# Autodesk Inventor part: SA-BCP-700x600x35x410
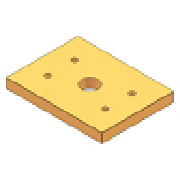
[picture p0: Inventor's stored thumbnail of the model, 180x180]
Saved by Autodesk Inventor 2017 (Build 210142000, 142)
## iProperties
Created: 2016-02
Part Number: SA-BCP-700x600x35x410
Material: S 55 C
Description: Bottom Clamping Plate
Document SubType Name: Modeling
Designer: Sandeep
Standard Revision: 1
Manufacturer: FUTABA
Language: en-US
Size Designation: 700x600x35x410
Categories: <MemberInstance><Categories><Category DisplayName="Mold" InternalName="349578f2-f4d4-4954-8c09-8e99297a61c0" Mnemonic="MOLD"><Category DisplayName="Mold Plates"
Density: 7.85 g/cm^3
Appearance: Orange (Pale)
IsCustomPart: 1
Author: Sandeep
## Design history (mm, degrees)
sketch "Sketch1"
  geometry: L1 (-300, 350)-(300, 350); L2 (300, 350)-(300, -350); L3 (300, -350)-(-300, -350); L4 (-300, -350)-(-300, 350); C1 r 17.5 at (0, 0); 4 further points
  constraints: 8 end point, 2 midpoint, 2 parallel, 1 centre point, 1 coincident, 1 horizontal, 1 horizontal alignment, 1 perpendicular, 1 vertical alignment
  dimensions: "d72" = 600 distance between parallel lines of L2 L4 (= W_); "d73" = 700 distance between parallel lines of L3 L1 (= L); "d74" = 35 diameter of C1 (= dB); "d75" = 205 horizontal distance of point (0, 0) point (-205, 243) (= 0.5 x S1_W); "d76" = 243 vertical distance of point (0, 0) point (-205, 243) (= 0.5 x S1_L)
body "Solid1"
extrude "Extrusion1" new body sketch "Sketch1" distance "d77" = 35 (= H_); taper "d78" = 0 deg
hole "Hole1" sketch "Sketch1" diameter "d79" = 18 (= S1_d1); stored, may be unused: countersink angle "d83" = 90 deg, drill point angle "d85" = 0 deg; dims "d80" = 6, "d81" = 26 (= S1_d2), "d82" = 17.5 (= S1_k), "d84" = 35 (= H_)
pattern_linear "Rectangular Pattern1" dims "d88" = 243 (computed from S1_L, Ns), "d91" = 410 (computed from S1_W, Nw)
extrude "Extrusion2" cut sketch "Sketch1" distance "d92" = 35 (= H_); taper "d93" = 0 deg
chamfer "Chamfer1" distance "d94" = 0.5; stored, may be unused: second distance "d95" = 2, angle "d96" = 45 deg
other parameters: "L" = 700 [user parameter; used in 1 equation term], "W_" = 600 [user parameter; used in 1 equation term], "H_" = 35 [user parameter; used in 3 equation terms], "S1_d1" = 18 [user parameter; used in 1 equation term], "S1_d2" = 26 [user parameter; used in 1 equation term], "S1_k" = 17.5 [user parameter; used in 1 equation term], "S1_L" = 486 [user parameter; used in 2 equation terms], "dB" = 35 [user parameter; used in 1 equation term]
